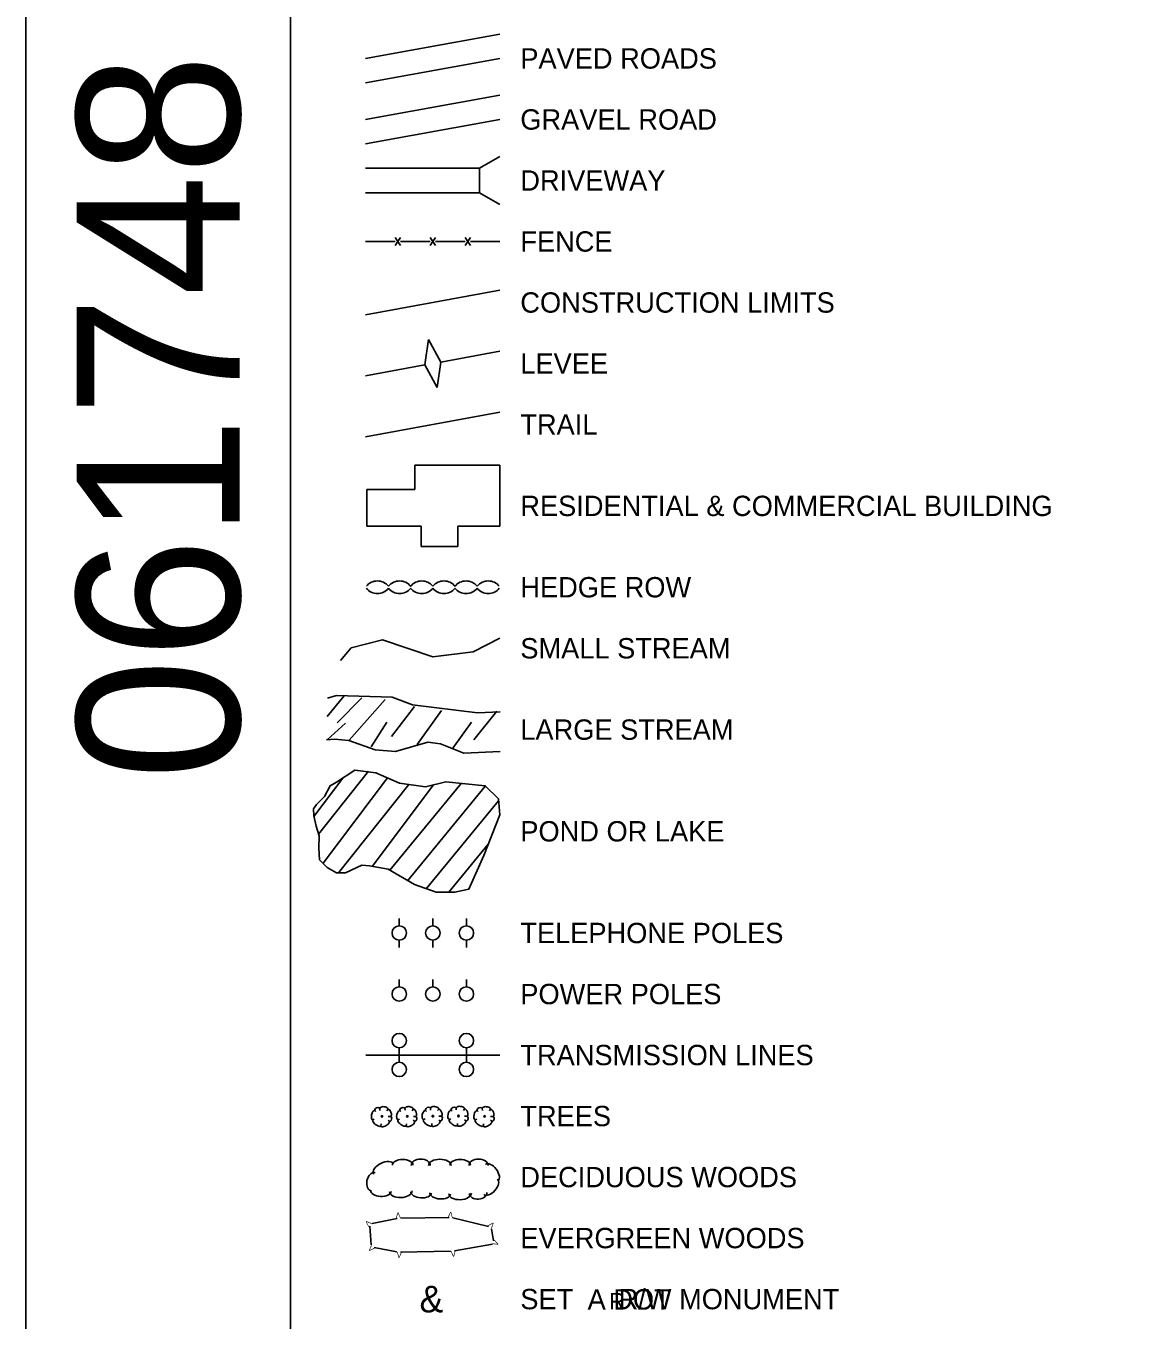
# Model space of a CAD drawing. Extents: x -3711 to 825, y -151 to 1050.
# Drawn here: x -3710.7 to -3435, y 302.7 to 620.9 of the extents above; entities that cross this region are included whole.
import ezdxf

# ---------------------------------------------------------------- set-up
doc = ezdxf.new("R2010")
doc.units = 0
for name, color, linetype in [('E_Sheet Border', 7, 'Continuous'), ('E_Title Sheet', 7, 'Continuous'), ('R_No Plot', 7, 'Continuous')]:
    doc.layers.add(name, color=color, linetype=linetype)

msp = doc.modelspace()

# ---------------------------------------------------------------- linework, layer by layer
at = {"layer": 'E_Sheet Border'}
msp.add_lwpolyline([(-3710.7, 0), (-2060.7, 0), (-2060.7, 1050), (-3710.7, 1050)], close=True, dxfattribs=at)
at = {"layer": 'E_Title Sheet'}
for p, q in [((-3627.22, 612.86), (-3594.22, 618.86)), ((-3594.22, 612.86), (-3627.22, 606.86)), ((-3627.22, 597.86), (-3594.22, 603.86)), ((-3594.22, 597.86), (-3627.22, 591.86)), ((-3599.22, 585.86), (-3594.22, 588.75)), ((-3627.22, 585.86), (-3599.22, 585.86)), ((-3599.22, 579.86), (-3599.22, 585.86)), ((-3627.22, 579.86), (-3599.22, 579.86)), ((-3599.22, 579.86), (-3594.22, 576.98)), ((-3619.98, 567.86), (-3627.22, 567.86)), ((-3619.98, 568.86), (-3618.63, 566.86)), ((-3618.63, 568.86), (-3619.98, 566.86)), ((-3611.39, 567.86), (-3618.63, 567.86)), ((-3611.39, 568.86), (-3610.04, 566.86)), ((-3610.04, 568.86), (-3611.39, 566.86)), ((-3602.8, 567.86), (-3610.04, 567.86)), ((-3602.8, 568.86), (-3601.46, 566.86)), ((-3601.46, 568.86), (-3602.8, 566.86)), ((-3594.22, 567.86), (-3601.46, 567.86)), ((-3594.22, 555.86), (-3627.22, 549.86)), ((-3611.79, 543.77), (-3612.68, 537.5)), ((-3608.75, 538.22), (-3611.79, 543.77)), ((-3609.64, 531.96), (-3608.75, 538.22)), ((-3594.22, 540.86), (-3608.75, 538.22)), ((-3612.68, 537.5), (-3627.22, 534.86)), ((-3612.68, 537.5), (-3609.64, 531.96)), ((-3594.22, 525.86), (-3627.22, 519.86)), ((-3615.14, 512.86), (-3615.14, 506.86)), ((-3615.14, 512.86), (-3594.22, 512.86)), ((-3594.22, 512.86), (-3594.22, 497.86)), ((-3626.9, 506.86), (-3615.14, 506.86)), ((-3626.9, 506.86), (-3626.9, 497.86)), ((-3626.9, 497.86), (-3613.62, 497.86)), ((-3613.62, 497.86), (-3613.62, 492.86)), ((-3604.58, 497.86), (-3594.22, 497.86)), ((-3604.58, 497.86), (-3604.58, 492.86)), ((-3613.62, 492.86), (-3604.58, 492.86)), ((-3618.96, 399.63), (-3618.96, 401.41)), ((-3610.71, 399.63), (-3610.71, 401.41)), ((-3602.46, 399.63), (-3602.46, 401.41)), ((-3618.96, 396.09), (-3618.96, 394.32)), ((-3610.71, 396.09), (-3610.71, 394.31)), ((-3602.46, 396.09), (-3602.46, 394.32)), ((-3618.96, 384.63), (-3618.96, 386.41)), ((-3610.71, 384.63), (-3610.71, 386.41)), ((-3602.46, 384.63), (-3602.46, 386.41)), ((-3618.97, 369.63), (-3618.97, 367.86)), ((-3602.47, 369.63), (-3602.47, 367.86)), ((-3594.22, 367.86), (-3627.21, 367.86)), ((-3618.97, 366.09), (-3618.97, 367.86)), ((-3602.47, 366.09), (-3602.47, 367.86)), ((-3624.98, 354.2), (-3624.75, 353.94)), ((-3623.75, 354.73), (-3623.73, 354.26)), ((-3621.73, 354.51), (-3622.01, 354.15)), ((-3618.79, 354.21), (-3618.56, 353.96)), ((-3617.56, 354.74), (-3617.54, 354.27)), ((-3615.55, 354.53), (-3615.82, 354.17)), ((-3612.51, 354.25), (-3612.28, 354)), ((-3611.29, 354.78), (-3611.26, 354.31)), ((-3609.27, 354.56), (-3609.54, 354.21)), ((-3606.2, 354.29), (-3605.97, 354.04)), ((-3604.97, 354.82), (-3604.95, 354.35)), ((-3602.95, 354.6), (-3603.22, 354.25)), ((-3599.8, 354.2), (-3599.57, 353.94)), ((-3598.58, 354.72), (-3598.55, 354.26)), ((-3596.56, 354.51), (-3596.83, 354.15)), ((-3625.47, 351.94), (-3625.09, 352.09)), ((-3623.47, 350.43), (-3623.4, 350.94)), ((-3621.42, 351.6), (-3621.7, 351.81)), ((-3621.05, 352.75), (-3621.69, 352.75)), ((-3619.28, 351.95), (-3618.9, 352.11)), ((-3617.28, 350.44), (-3617.21, 350.95)), ((-3615.24, 351.61), (-3615.51, 351.82)), ((-3614.86, 352.77), (-3615.5, 352.77)), ((-3613.01, 351.99), (-3612.62, 352.15)), ((-3611, 350.48), (-3610.94, 351)), ((-3608.96, 351.65), (-3609.24, 351.87)), ((-3608.58, 352.81), (-3609.22, 352.81)), ((-3606.69, 352.03), (-3606.31, 352.19)), ((-3604.68, 350.52), (-3604.62, 351.04)), ((-3602.64, 351.69), (-3602.92, 351.91)), ((-3602.26, 352.85), (-3602.9, 352.85)), ((-3600.3, 351.94), (-3599.91, 352.09)), ((-3598.29, 350.43), (-3598.23, 350.94)), ((-3596.25, 351.6), (-3596.53, 351.81)), ((-3595.87, 352.75), (-3596.51, 352.75)), ((-3606.7, 327.93), (-3618.58, 327.75)), ((-3597.02, 325.7), (-3605.78, 327.8)), ((-3626.23, 325.76), (-3625.84, 321.2)), ((-3619.47, 327.66), (-3625.62, 326.44)), ((-3595.78, 322.2), (-3596.29, 325.15)), ((-3605.43, 319.72), (-3596.03, 321.39)), ((-3625.15, 320.56), (-3619.59, 319.5)), ((-3618.64, 319.41), (-3606.35, 319.62))]:
    msp.add_line(p, q, dxfattribs=at)
for points in [[(-3645.7, 60), (-3645.7, 990)], [(-3633.43, 464.84), (-3630.78, 467.93), (-3623.06, 469.91), (-3610.73, 465.74), (-3600.8, 466.99), (-3594.22, 470.36)], [(-3636.65, 451.09), (-3632.48, 456.16)], [(-3636.63, 455.63), (-3634.42, 456.21), (-3620.68, 455.83), (-3615.72, 453.92), (-3599.7, 452.02), (-3594.21, 452.27)], [(-3634.18, 449.51), (-3628.15, 455.69)], [(-3631.31, 445.29), (-3622.42, 455.24)], [(-3615.18, 453.58), (-3620.91, 446.2)], [(-3614.58, 444.23), (-3608.55, 452.53)], [(-3594.98, 452.38), (-3600.63, 445.37)], [(-3636.7, 445.37), (-3632.14, 449.42)], [(-3625.89, 443.63), (-3622, 449.67)], [(-3605.84, 443.33), (-3601.18, 449.7)], [(-3594.21, 442.44), (-3603.13, 442.09), (-3608.85, 444.38), (-3611.91, 444.76), (-3619.92, 442.48), (-3624.88, 442.86), (-3631.37, 445.15), (-3634.8, 445.53), (-3636.81, 445.36)], [(-3618.93, 434.66), (-3624.74, 437.24), (-3629.85, 437.89), (-3634.38, 434.9), (-3635.97, 434.06), (-3637.34, 431.38), (-3639.31, 429.46), (-3640.02, 428.39), (-3639.96, 426.64), (-3639.39, 424.09), (-3638.65, 421.71), (-3638.74, 418.72), (-3638.56, 415.87), (-3636.66, 413.98), (-3634.36, 412.61), (-3632.18, 412.68), (-3628.12, 414.54), (-3626.27, 414.35), (-3621.69, 413.58), (-3615.2, 409.77), (-3609.86, 407.86), (-3605.28, 407.86), (-3601.85, 408.62), (-3598.17, 416.91), (-3594.22, 426.94), (-3594.62, 430.88), (-3597.82, 434.07), (-3607.52, 435.02), (-3612.53, 433.81), (-3618.93, 434.66)], [(-3639.93, 426.5), (-3632.82, 435.93)], [(-3638.79, 422.16), (-3626.51, 437.62)], [(-3637.69, 415), (-3621.88, 435.97)], [(-3633.89, 412.62), (-3616.63, 434.35)], [(-3625.63, 414.24), (-3610.52, 434.29)], [(-3621.28, 413.34), (-3603.74, 434.65)], [(-3616.88, 410.76), (-3597.75, 434)], [(-3612.34, 408.75), (-3594.57, 430.33)], [(-3606.81, 407.86), (-3597.08, 419.67)]]:
    msp.add_lwpolyline(points, dxfattribs=at)
for centre, radius in [((-3618.96, 397.86), 1.77), ((-3610.72, 397.86), 1.77), ((-3602.47, 397.86), 1.77), ((-3618.96, 382.86), 1.77), ((-3610.72, 382.86), 1.77), ((-3602.47, 382.86), 1.77), ((-3618.97, 371.41), 1.77), ((-3602.46, 371.41), 1.77), ((-3618.97, 364.32), 1.77), ((-3602.47, 364.32), 1.77), ((-3623.19, 352.77), 0.188), ((-3617, 352.78), 0.188), ((-3610.72, 352.82), 0.188), ((-3604.41, 352.87), 0.188), ((-3598.01, 352.77), 0.188)]:
    msp.add_circle(centre, radius, dxfattribs=at)
for centre, start, end in [((-3624.33, 480.91), 38.9448, 141.0552), ((-3618.88, 480.91), 38.9448, 141.0552), ((-3613.44, 480.91), 38.9448, 141.0552), ((-3607.99, 480.91), 38.9448, 141.0552), ((-3602.55, 480.91), 38.9448, 141.0552), ((-3597.1, 480.91), 38.9448, 141.0552), ((-3624.33, 484.81), 218.9448, 321.0552), ((-3618.88, 484.81), 218.9448, 321.0552), ((-3613.44, 484.81), 218.9448, 321.0552), ((-3607.99, 484.81), 218.9448, 321.0552), ((-3602.55, 484.81), 218.9448, 321.0552), ((-3597.1, 484.81), 218.9448, 321.0552)]:
    msp.add_arc(centre, 3.5, start, end, dxfattribs=at)
for centre, major_axis, ratio, start_param, end_param in [((-3625.22, 353.06), (-0.25, -1.13), 0.482993, 3.141593, 6.283185), ((-3624.38, 354.45), (-0.603, -0.255), 0.711532, 3.141592, 6.283185), ((-3622.74, 354.62), (1.01, -0.11), 0.529943, 0, 3.141593), ((-3621.38, 353.63), (0.337, -0.882), 0.420543, 6.283185, 9.424777), ((-3619.03, 353.08), (-0.25, -1.13), 0.482993, 3.141593, 6.283185), ((-3618.19, 354.47), (-0.603, -0.255), 0.711532, 3.141592, 6.283185), ((-3616.56, 354.63), (1.01, -0.11), 0.529943, 0, 3.141593), ((-3615.2, 353.65), (0.337, -0.882), 0.420543, 6.283185, 9.424777), ((-3612.75, 353.12), (-0.25, -1.13), 0.482993, 3.141593, 6.283185), ((-3611.91, 354.51), (-0.603, -0.255), 0.711532, 3.141592, 6.283185), ((-3610.28, 354.67), (1.01, -0.11), 0.529943, 0, 3.141593), ((-3608.92, 353.69), (0.337, -0.882), 0.420543, 6.283185, 9.424777), ((-3606.44, 353.16), (-0.25, -1.13), 0.482993, 3.141593, 6.283185), ((-3605.6, 354.55), (-0.603, -0.255), 0.711532, 3.141592, 6.283185), ((-3603.96, 354.71), (1.01, -0.11), 0.529943, 0, 3.141593), ((-3602.6, 353.73), (0.337, -0.882), 0.420543, 6.283185, 9.424777), ((-3600.04, 353.06), (-0.25, -1.13), 0.482993, 3.141593, 6.283185), ((-3599.2, 354.45), (-0.603, -0.255), 0.711532, 3.141592, 6.283185), ((-3597.57, 354.62), (1.01, -0.11), 0.529943, 0, 3.141593), ((-3596.21, 353.63), (0.337, -0.882), 0.420543, 6.283185, 9.424777), ((-3624.47, 351.18), (1, -0.75), 0.405112, 3.141593, 6.283186), ((-3622.45, 351), (-1.03, -0.6), 0.471017, 0, 3.141593), ((-3621.22, 352.17), (-0.169, -0.567), 0.646762, 0, 3.141593), ((-3618.28, 351.19), (1, -0.75), 0.405112, 3.141593, 6.283186), ((-3616.26, 351.01), (-1.03, -0.6), 0.471017, 0, 3.141593), ((-3615.03, 352.18), (-0.169, -0.567), 0.646762, 0, 3.141593), ((-3612.01, 351.23), (1, -0.75), 0.405112, 3.141593, 6.283186), ((-3609.99, 351.05), (-1.03, -0.6), 0.471017, 0, 3.141593), ((-3608.75, 352.22), (-0.169, -0.567), 0.646762, 0, 3.141593), ((-3605.69, 351.28), (1, -0.75), 0.405112, 3.141593, 6.283186), ((-3603.67, 351.1), (-1.03, -0.6), 0.471017, 0, 3.141593), ((-3602.43, 352.26), (-0.169, -0.567), 0.646762, 0, 3.141593), ((-3599.29, 351.18), (1, -0.75), 0.405112, 3.141593, 6.283186), ((-3597.28, 351), (-1.03, -0.6), 0.471017, 0, 3.141593), ((-3596.04, 352.17), (-0.169, -0.567), 0.646762, 0, 3.141593), ((-3622.82, 339.85), (-2.48, -1.24), 0.55008, 3.141593, 6.283185), ((-3618.13, 340.8), (-2.53, 0), 0.540699, 3.141593, 6.283185), ((-3613.7, 340.68), (-2.34, 0), 0.685311, 3.141593, 6.283185), ((-3608.98, 340.72), (-2.77, 0), 0.55008, 3.141593, 6.283185), ((-3604, 340.8), (-2.53, 0), 0.540699, 3.141593, 6.283185), ((-3599.48, 340.68), (-2.34, 0), 0.685311, 3.141593, 6.283185), ((-3596.22, 338.96), (-1.52, 2.02), 0.540699, 3.141593, 6.283185), ((-3625.32, 336.68), (-0.44, -2.3), 0.685311, 3.141593, 6.283185), ((-3596.48, 335.45), (1.67, 1.9), 0.540699, 3.141593, 6.283185), ((-3623.49, 334.45), (2.52, -0.16), 0.540699, 3.141593, 6.283185), ((-3618.59, 334.34), (2.77, 0.12), 0.55008, 3.141593, 6.283185), ((-3613.61, 334.1), (2.52, -0.16), 0.540699, 3.141593, 6.283185), ((-3599.57, 333.96), (2.17, 0.13), 0.702692, 3.141593, 6.283185), ((-3608.93, 333.84), (2.52, -0.16), 0.540699, 3.141593, 6.283185), ((-3604.02, 333.82), (2.77, 0.12), 0.55008, 3.141593, 6.283185)]:
    msp.add_ellipse(centre, major_axis=major_axis, ratio=ratio, start_param=start_param, end_param=end_param, dxfattribs=at)
at = {"layer": 'R_No Plot'}
msp.add_lwpolyline([(-3710.7, 0), (-2060.7, 0), (-2060.7, 1050), (-3710.7, 1050)], close=True, dxfattribs=at)

# ---------------------------------------------------------------- texts
at = {"layer": 'E_Title Sheet'}
for s, height, p in [('PAVED ROADS', 5, (-3589.22, 610.36)), ('GRAVEL ROAD', 5, (-3589.22, 595.36)), ('DRIVEWAY', 5, (-3589.22, 580.36)), ('FENCE', 5, (-3589.22, 565.36)), ('CONSTRUCTION LIMITS', 5, (-3589.22, 550.36)), ('LEVEE', 5, (-3589.22, 535.36)), ('TRAIL', 5, (-3589.22, 520.36)), ('RESIDENTIAL & COMMERCIAL BUILDING', 5, (-3589.22, 500.36)), ('HEDGE ROW', 5, (-3589.22, 480.36)), ('SMALL STREAM', 5, (-3589.22, 465.36)), ('LARGE STREAM', 5, (-3589.22, 445.36)), ('POND OR LAKE', 5, (-3589.22, 420.36)), ('TELEPHONE POLES', 5, (-3589.22, 395.36)), ('POWER POLES', 5, (-3589.22, 380.36)), ('TRANSMISSION LINES', 5, (-3589.22, 365.36)), ('TREES', 5, (-3589.22, 350.36)), ('DECIDUOUS WOODS', 5, (-3589.22, 335.36)), ('EVERGREEN WOODS', 5, (-3589.22, 320.36)), ('&', 6.55, (-3613.99, 304.59)), ('SET      R/W MONUMENT', 5, (-3589.22, 305.36)), ('A DOT', 5, (-3572.69, 305.29)), ('R', 4, (-3567.38, 305.35))]:
    msp.add_text(s, height=height, dxfattribs=at).set_placement(p)
for s, height, rotation, p in [('061748', 40, 90, (-3658.2, 435.49)), ('V', 1.42, 184.6345, (-3618.68, 329.2)), ('V', 1.42, 174.4346, (-3605.67, 329.24)), ('V', 1.42, 226.0752, (-3626.68, 327.44)), ('V', 1.42, 139.2703, (-3595.35, 326.2)), ('V', 1.42, 63.4333, (-3594.93, 320.76)), ('V', 1.42, 316.0355, (-3626.81, 320.2)), ('V', 1.42, 356.9247, (-3619.65, 318.03)), ('V', 1.42, 5.0182, (-3606.24, 318.22))]:
    msp.add_text(s, height=height, rotation=rotation, dxfattribs=at).set_placement(p)

doc.saveas('drawing.dxf')
